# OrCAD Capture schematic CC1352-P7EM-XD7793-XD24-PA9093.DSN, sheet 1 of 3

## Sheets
1 Mechanical: size A4; title: CC1352-P7EM-XD7793-XD24-PA9093; rev: B0
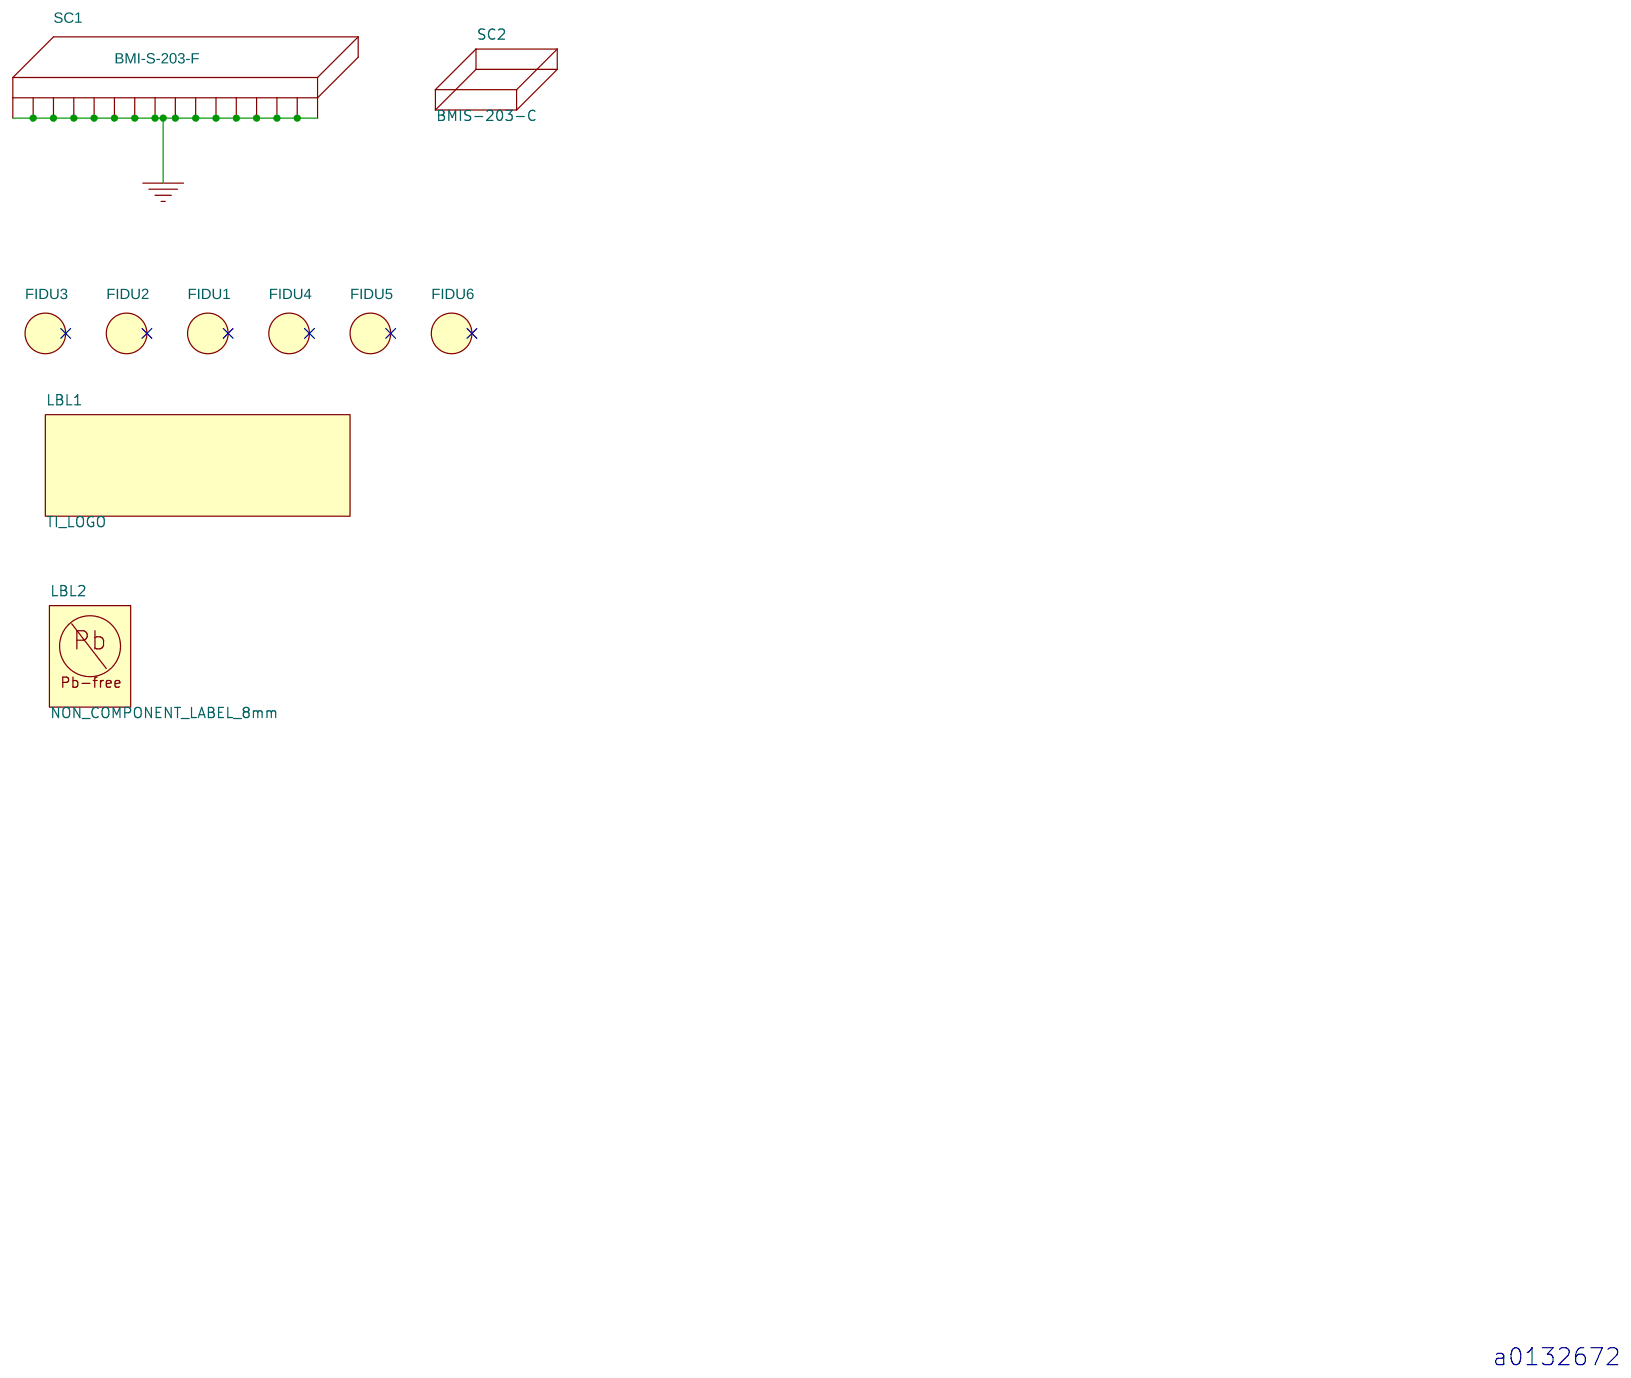
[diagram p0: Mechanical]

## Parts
FIDU1  FIDU_1MM  [FID100X115B]
FIDU2  FIDU_1MM  [FID100X115B]
FIDU3  FIDU_1MM  [FID100X115B]
FIDU4  FIDU_1MM  [FID100X115B]
FIDU5  FIDU_1MM  [FID100X115B]
FIDU6  FIDU_1MM  [FID100X115B]
LBL1  TI_LOGO  [TI_LOGO_1]
LBL2  NON_COMPONENT_LABEL_8mm  [LABEL_PB-FREE_8MM_A2N]
SC1  BMI-S-203-F  [MECH_BMIS203_A2N]
SC2  BMIS-203-C  [MECH_BMIS203C]

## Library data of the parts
FIDU1-FIDU6 = FIDMARK: NON COMPONENT, FIDUCIAL MARK, ROUND 1mm, SMD; Additional Datasheet URL: N/A; AutoDoc File: https://notefied-dynamic-precision.com/DB/Apps/Desktop/Item/Object.aspx?id=74548; BU Name: DYNAMIC PRECISION GDANSK; CLASS: IO; Country of Origin: Missing Info; Datasheet URL: N/A; Mass: N/A; Mounting Type: SMD; NOTEfied URL: https://notefied-dynamic-precision.com/NOTEfiedWebInterface/part/show?partNumber=19-00111; Old Footprint: FID100X115; Packing Size: N/A; Packing Type: Missing Info; Part Number: 19-00111; Part Type: Non Component|FIDUCIAL; ROHS: Compliant; Revision: R015; Status: Released; Type: Non Component; Vendor: NON_COMPONENT; Vendor Part Number: FIDUCIAL_1mm; Vendor Part Status: Active
LBL1 = TI_LOGO_V1: NON COMPONENT, LABEL, TEXAS INSTRUMENTS LOGO; Additional Datasheet URL: N/A; AutoDoc File: https://notefied-dynamic-precision.com/DB/Apps/Desktop/Item/Object.aspx?id=87770; BU Name: TEXAS INSTRUMENTS NORWAY; Country of Origin: Missing Info; Datasheet URL: N/A; Exclusive for Customers: TEXAS INSTRUMENTS NORWAY; Mass: N/A; Mounting Type: Not Apply; NOTEfied URL: https://notefied-dynamic-precision.com/NOTEfiedWebInterface/part/show?partNumber=19-00350; Notes: Custom Item; Packing Size: N/A; Packing Type: Missing Info; Part Number: 19-00350; Part Type: Non Component|LABEL; ROHS: Missing Info; Revision: R014; Status: Released; Texas Part Status: Under Review; Type: Non Component; Vendor: NON_COMPONENT; Vendor Part Status: Active
LBL2 = LABEL_Pb-free_V1: NON COMPONENT, LABEL, PB-FREE, 8mm; Additional Datasheet URL: N/A; AutoDoc File: https://notefied-dynamic-precision.com/DB/Apps/Desktop/Item/Object.aspx?id=57438; BU Name: DYNAMIC PRECISION GDANSK; Country of Origin: Missing Info; Datasheet URL: N/A; Mass: N/A; Mounting Type: Not Apply; NOTEfied URL: https://notefied-dynamic-precision.com/NOTEfiedWebInterface/part/show?partNumber=19-00159; Packing Size: N/A; Packing Type: Missing Info; Part Number: 19-00159; Part Type: Non Component|LABEL; ROHS: Missing Info; Revision: R011; Status: Released; Type: Non Component; Vendor: NON_COMPONENT; Vendor Part Status: Active
SC1 = SHIELD_COVER_BMIS-203: MECHANIC, FRAME FOR SHIELD BMI-S-203, SMD; Additional Datasheet URL: https://www.laird.com/sites/default/files/2018-11/EMI-CAT-Essentials%201213.pdf; AutoDoc File: https://notefied-dynamic-precision.com/DB/Apps/Desktop/Item/Object.aspx?id=57168; BU Name: DYNAMIC PRECISION GDANSK; Budget Currency: EUR; Budget Price: 1.11; Budgetary Price: 0.46087 USD; CLASS: IC; Client Status: UNDER_REVIEW; Country of Origin: Czech Republic; Datasheet URL: https://www.laird.com/sites/default/files/2018-11/Board%20Level%20Shields%20Catalog%20Download.pdf; Datasheet URL 1: http://cdn.lairdtech.com/home/brandworld/files/Board%20Level%20Shields%20Catalog%20Download.pdf; Datasheet URL 2: http://cdn.lairdtech.com/home/brandworld/files/EMI-CAT-Essentials%201213.pdf; Lead Time: 4; Mass: 1g; Max Oper Temp: +85DEGC; Maximum Operating Temperature: +85DEGC; Min Oper Temp: -40DEGC; Minimum Operating Temperature: -40DEGC; Mounting Type: SMD; NOTEfied URL: https://notefied-dynamic-precision.com/NOTEfiedWebInterface/part/show?partNumber=13-00133; Packing Size: 300; Packing Type: Tape & Reel; Part Number: 13-00133; Part Type: Mechanic|SHIELD; REACH/SVHC Compliance: Compliant; REACH/SVHC Details: SVHC List Version Jan 15, 2018; REACH/SVHC Source: REACH Declaration; REACH/SVHC Status: Unaffected; ROHS: Compliant; Revision: R017; RoHS Status: ROHS_COMPLIANT; Status: Released; Texas Part Status: Under Review; Type: Mechanic; Vendor: LAIRD; Vendor Part Status: Active; Weight: 1g
SC2 = SHIELD_COVER: MECHANIC, COVER FOR SHIELD BMI-S-203; Additional Datasheet URL: https://www.laird.com/sites/default/files/2018-11/EMI-CAT-Essentials%201213.pdf; Budgetary Price: 0.85209 USD; Country of Origin: Czech Republic; Datasheet URL: https://www.laird.com/sites/default/files/2018-11/Board%20Level%20Shields%20Catalog%20Download.pdf; Lead Time: 5; Mass: 1g; Maximum Operating Temperature: +85DEGC; Minimum Operating Temperature: -40DEGC; Mounting Type: Not Apply; NOTEfied URL: https://notefied-dynamic-precision.com/NOTEfiedWebInterface/part/show?partNumber=13-00422; Packing Size: 300; Packing Type: Tape & Reel; Part Number: 13-00422; Part Type: Mechanic|SHIELD; REACH/SVHC Compliance: Compliant; REACH/SVHC Details: SVHC List Version Jan 12, 2017; REACH/SVHC Source: REACH Declaration; REACH/SVHC Status: Unaffected; ROHS: Compliant; Revision: R015; Status: Released; Texas Part Status: Under Review; Type: Mechanic; Vendor: LAIRD; Vendor Part Number: BMI-S-203-C; Vendor Part Status: Active

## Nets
GND: SC1.1(GND) SC1.2(GND) SC1.3(GND) SC1.4(GND) SC1.5(GND) SC1.6(GND) SC1.7(GND) SC1.8(GND) SC1.9(GND) SC1.10(GND) SC1.11(GND) SC1.12(GND) SC1.13(GND) SC1.14(GND) SC1.15(GND) SC1.16(GND) ; also on sheet 2

Not connected (* = marked no-connect by the designer): FIDU1 1*; FIDU2 1*; FIDU3 1*; FIDU4 1*; FIDU5 1*; FIDU6 1*

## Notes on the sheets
sheet 1
- a0132672
